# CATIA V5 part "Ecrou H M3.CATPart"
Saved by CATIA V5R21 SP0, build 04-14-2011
Part number: Ecrou H M3
Material "Acier": density 7860 kg/m3, Young's modulus 2e+11 Pa, Poisson ratio 0.266, thermal expansion 1.17e-05 1/K
Bounding box of the stored display mesh (mm): x -2.5 to 2.5, y -2.887 to 2.887, z 0 to 2
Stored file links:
  C:\Users\Olivier\Desktop\redaction CATIA (local)\CATIA\DONNEES\Exercice assemblage 3 (Pompe de ventilation)\Assemblage ensemble bloc moteur (Product inclus)\Ecrou H M3.CATPart
  C:\Program Files\Dassault Systemes\B21\win_b64\startup\materials\French\Catalog.CATMaterial
  C:\Users\Olivier\Desktop\redaction CATIA (local)\CATIA\DONNEES\Exercice assemblage 3 (Pompe de ventilation)\Assemblage ensemble bloc moteur (Product inclus)\CATIA_EnvironmentMap_Satin_512x512.jpg
  C:\Users\Olivier\Desktop\redaction CATIA (local)\pompe à moteur de ventilation refait\Pompe_a_moteur_de_ventilation.CATProduct
  C:\Users\Olivier\Desktop\redaction CATIA (local)\pompe à moteur de ventilation refait\Ecrou a collerette M5.CATPart
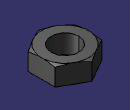
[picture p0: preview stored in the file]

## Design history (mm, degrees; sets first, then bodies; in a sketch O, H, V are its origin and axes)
Body1 (main body), material "Acier"
  Sketch1 on xy-plane, origin (0, 0, 0), H (1, 0, 0), V (0, 1, 0)
    circle A1 centre (0, 0) radius 1.5
    point P1 (2.5, -1.4434)
    point P2 (2.5, 1.4434)
    point P3 (0, 2.8868)
    point P4 (-2.5, 1.4434)
    point P5 (-2.5, -1.4434)
    point P6 (0, -2.8868)
    point P7 (2.5, 0)
    line L1 (2.5, -1.4434) -> (2.5, 1.4434)
    line L2 (2.5, 1.4434) -> (0, 2.8868)
    line L3 (0, 2.8868) -> (-2.5, 1.4434)
    line L4 (-2.5, 1.4434) -> (-2.5, -1.4434)
    line L5 (-2.5, -1.4434) -> (0, -2.8868)
    line L6 (0, -2.8868) -> (2.5, -1.4434)
    construction line L7 (0, 0) -> (2.5, 0)
    construction circle A2 centre (0, 0) radius 2.8868
    construction arc A3 centre (-2.5, -1.4434) radius 2.8868 from (-2.5, 1.4434) to (0, -2.8868) cw
    construction arc A4 centre (2.5, 1.4434) radius 2.8868 from (0, 2.8868) to (2.5, -1.4434) ccw
    distance L1 L4 = 5
    horizontal: L7 H
    coincidence: A2 P1, A2 P2, A2 P3, A2 P4, A2 P5, A2 P6, A3 O, A4 O
    midpoint: P7 L1
  Pad1: profile Sketch1, direction (0, 0, 1), length 2
  Sketch2 on yz-plane, origin (0, 0, 0), H (0, 1, 0), V (0, 0, 1)
    line L1 (2.4595, 2.0276) -> (2.9071, 2.0276)
    point P1 (2.4595, 2.0276)
    line L2 (2.9071, 2.0276) -> (2.9071, 1.8177)
    line L3 (2.9071, 1.8177) -> (2.4663, 2.0244)
    horizontal: L1 H
    vertical: L2 V
    coincidence: L3 P1
  Groove1: profile Sketch2, axis Sketch2.V, angle 360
